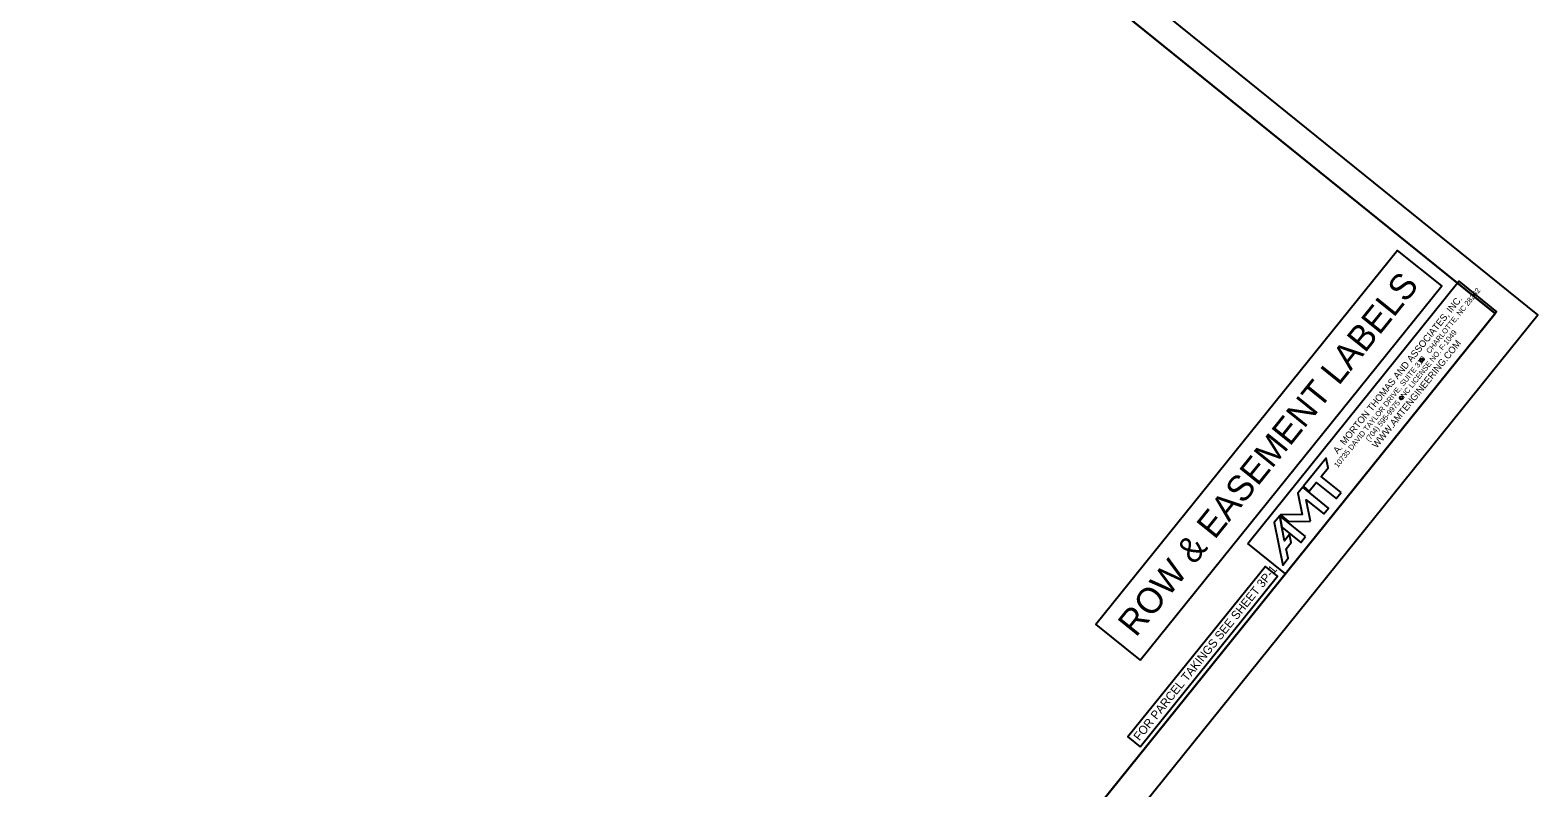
# Model space of a CAD drawing. Extents: x 1487825 to 1489784, y 498345 to 500343.
# Drawn here: x 1488789 to 1489784, y 499344 to 499844 of the extents above; entities that cross this region are included whole.
import ezdxf

# ---------------------------------------------------------------- set-up
doc = ezdxf.new("R2010")
doc.units = 0
for name, color, linetype in [('Prop Grid Mask', 7, 'Continuous'), ('Prop Horizontal Alignment Curve and Spiral Data', 7, 'Continuous'), ('Sheet Block Title CELL', 7, 'Continuous'), ('Sheet Clip Boundary CELL', 7, 'Continuous'), ('Sheet Plan CELL', 7, 'Continuous'), ('Sheet Plot Border Outside CELL', 7, 'Continuous')]:
    doc.layers.add(name, color=color, linetype=linetype)

msp = doc.modelspace()

# ---------------------------------------------------------------- linework, layer by layer
at = {"layer": 'Prop Grid Mask'}
for points in [[(1489521.9, 499428.1), (1489720.91, 499674.89), (1489691.78, 499698.38), (1489492.76, 499451.59)], [(1489592.92, 499505.14), (1489732.31, 499677.98), (1489757.18, 499657.92), (1489617.8, 499485.08)], [(1489521.84, 499371.02), (1489612.58, 499483.54), (1489604.54, 499490.01), (1489513.81, 499377.5)]]:
    msp.add_lwpolyline(points, close=True, dxfattribs=at)
at = {"layer": 'Sheet Block Title CELL'}
msp.add_lwpolyline([(1489592.92, 499505.14), (1489732.31, 499677.98), (1489757.18, 499657.92), (1489617.8, 499485.08)], close=True, dxfattribs=at)
for points in [[(1489654.5, 499538.63), (1489641.33, 499549.25), (1489645.91, 499554.92), (1489644.63, 499561.36), (1489629.64, 499542.77), (1489633.56, 499539.61), (1489638.17, 499545.33), (1489651.34, 499534.71), (1489654.5, 499538.63)], [(1489634.3, 499519.73), (1489631.49, 499533.97), (1489643.16, 499524.56), (1489646.32, 499528.48), (1489629.23, 499542.27), (1489626.07, 499538.35), (1489628.75, 499524.21), (1489614.43, 499523.91), (1489619.87, 499519.52), (1489634.3, 499519.73)], [(1489615.45, 499515.78), (1489614.02, 499523.41), (1489610.33, 499518.83), (1489615.98, 499490.86), (1489619.55, 499495.29), (1489618.28, 499501.57), (1489621.55, 499505.63), (1489620.57, 499511.03), (1489617.19, 499506.83), (1489615.45, 499515.78)], [(1489631.11, 499509.62), (1489614.02, 499523.41), (1489615.45, 499515.78), (1489627.95, 499505.7), (1489631.11, 499509.62)]]:
    msp.add_lwpolyline(points, dxfattribs=at)
for centre in [(1489707.73, 499626.1), (1489694.27, 499601.09)]:
    msp.add_circle(centre, 1, dxfattribs=at)
at = {"layer": 'Sheet Clip Boundary CELL'}
msp.add_lwpolyline([(1488948.36, 500051.16), (1488813.25, 500160.1), (1488087.84, 499260.53), (1488879.09, 498569.08), (1489756.18, 499656.68), (1489073.94, 500206.87)], close=True, dxfattribs=at)
at = {"layer": 'Sheet Plan CELL'}
for points in [[(1488938.86, 500315.83), (1487997.21, 499148.18), (1488814.55, 498489.05), (1489756.18, 499656.68)], [(1488814.55, 498489.05), (1487997.21, 499148.15), (1488813.25, 500160.1), (1488930.07, 500065.91), (1489055.66, 500221.61), (1489756.18, 499656.68)]]:
    msp.add_lwpolyline(points, close=True, dxfattribs=at)
at = {"layer": 'Sheet Plot Border Outside CELL'}
msp.add_lwpolyline([(1488727.56, 498345.32), (1489784.38, 499655.78), (1488932.01, 500343.17), (1487875.19, 499032.7)], close=True, dxfattribs=at)

# ---------------------------------------------------------------- texts
at = {"layer": 'Prop Horizontal Alignment Curve and Spiral Data'}
for s, height, p in [('ROW & EASEMENT LABELS', 16.875, (1489519.12, 499442.76)), ('FOR PARCEL TAKINGS SEE SHEET 3P-1.', 5.625, (1489521.38, 499374.6))]:
    msp.add_text(s, height=height, rotation=51.11565, dxfattribs=at).set_placement(p)
at = {"layer": 'Sheet Block Title CELL'}
for s, height, p in [('A. MORTON THOMAS AND ASSOCIATES, INC.', 4.5, (1489652.31, 499563.88)), ('10735 DAVID TAYLOR DRIVE, SUITE 310   CHARLOTTE, NC 28262', 3.5, (1489652.33, 499554.75)), ('(704) 595-9975   NC LICENSE NO. F-1049', 3.5, (1489672.98, 499571.99)), ('WWW.AMTENGINEERING.COM', 4.5, (1489678.07, 499567.55))]:
    msp.add_text(s, height=height, rotation=51.11516, dxfattribs=at).set_placement(p)

doc.saveas('drawing.dxf')
